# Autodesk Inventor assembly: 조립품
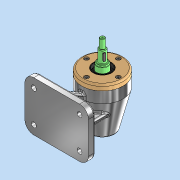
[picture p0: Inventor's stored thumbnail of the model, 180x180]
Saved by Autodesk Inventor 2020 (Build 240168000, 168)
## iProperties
Created: 2024-12
Part Number: 조립품
Document SubType Name: Assembly
Designer: 1강의실14
Author: 1강의실14
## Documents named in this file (9)
- C:\Users\1강의실14\Desktop\741204V1003\조립품.iam
- C:\Users\1강의실14\Desktop\741204V1003\본체.ipt
- C:\Users\1강의실14\Desktop\741204V1003\축.ipt
- C:\Users\1강의실14\Desktop\741204V1003\앵귤러 볼 베어링 7003A.ipt
- C:\Users\1강의실14\Desktop\741204V1003\앵귤러 볼 제어링 7204A.ipt
- C:\Users\1강의실14\Desktop\741204V1003\커버.ipt
- C:\Users\1강의실14\Desktop\741204V1003\오일 실 20 32 8.ipt
- C:\Users\1강의실14\Desktop\741204V1003\육각 소켓 머리 볼트 M4x10.ipt
- C:\Users\1강의실14\Desktop\741204V1003\평행 키 4x4x14.ipt
